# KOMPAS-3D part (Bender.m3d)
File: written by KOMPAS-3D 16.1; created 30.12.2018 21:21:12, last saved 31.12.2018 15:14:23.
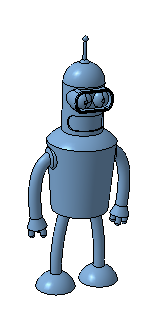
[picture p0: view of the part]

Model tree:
1. Эскиз:1
2. Операция вращения:1
     Угол 1 = 360
3. Эскиз:2
4. Операция выдавливания:1
     Расстояние 1 = 17.3; Угол 1 = 0.45
5. Скругление:1
     Радиус = 0.5
6. Скругление:2
     Радиус = 5
7. Смещенная плоскость:1
     Расстояние = 48
8. Эскиз:3
9. Вырезать элемент выдавливания:1
     Расстояние 1 = 10
10. Скругление:3
     Радиус = 5
11. Эскиз:4
12. Вырезать элемент выдавливания:2
     Расстояние 1 = 0.5
13. Эскиз:5
14. Операция вращения:2
     Угол 1 = 360
15. Эскиз:6
16. Операция вращения:3
     Угол 1 = 360
17. Эскиз:7
18. Эскиз:8
19. Кинематическая операция:1
20. Эскиз:9
21. Операция вращения:4
     Угол 1 = 360
22. Эскиз:10
23. Перпендикулярная плоскость:1
24. Эскиз:11
25. Кинематическая операция:2
26. Эскиз:12
27. Операция выдавливания:3
     Расстояние 1 = 7; Угол 1 = 20; Расстояние 2 = 0.5
28. Эскиз:13
29. Операция выдавливания:4
     Расстояние 1 = 7; Расстояние 2 = 0.5
30. Скругление:4
     Радиус = 2
31. Зеркальный массив:1
32. Экземпляр ( 1 )
33. Экземпляр ( 2 )  (with: Кинематическая операция:1, Операция вращения:4, Кинематическая операция:2, Операция выдавливания:3, Операция выдавливания:4, Скругление:4)

Referenced files in C:\Users\NIK\Desktop\bender\: bender_bending_rodriguez_3d_model_c4d_max_obj_fbx_ma_lwo_3ds_3dm_stl_1135635_o.png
